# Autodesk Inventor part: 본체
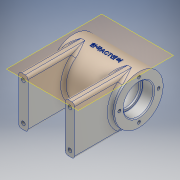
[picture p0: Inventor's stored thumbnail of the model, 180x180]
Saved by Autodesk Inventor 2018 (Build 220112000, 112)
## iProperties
Created: 2020-07
Part Number: 본체
Material: 알루미늄 6061
Document SubType Name: Modeling
Designer: Administrator
Density: 2.7 g/cm^3
Appearance: 알루미늄 - 평지
Mass: 305.265 g
Surface Area: 357.573 cm^2
Volume: 113.061 cm^3
Author: Administrator
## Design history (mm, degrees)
sketch "스케치1"
  geometry: L1 (-35, 0)-(35, 0); L2 (-35, 26)-(-35, 0); L3 (-35, 26)-(35, 26); L4 (35, 26)-(35, 0); L5 (-35, 16)-(-23, 16); L6 (-23, 16)-(-23, 14); L7 (-23, 14)-(-21, 14); L8 (-21, 14)-(-21, 21); L9 (-21, 21)-(21, 21); L10 (21, 21)-(21, 14); L11 (21, 14)-(23, 14); L12 (23, 14)-(23, 16); L13 (23, 16)-(35, 16); 3 further points
  constraints: 26 end point, 7 perpendicular, 6 point on line, 2 horizontal, 2 midpoint, 1 coincident, 1 vertical, 1 vertical alignment
  dimensions: "d0" = 70 distance of L1.start L1.end; "d1" = 32 diameter of L5 L1; "d2" = 42 diameter of L9 L1; "d3" = 52 diameter of L3 L1; "d4" = 12 distance of L5.start L5.end; "d5" = 12 distance of L12.end L13.end; "d7" = 28 diameter of L7 L1; "d8" = 42 distance of L8.end L9.end
revolve "회전1" sketch "스케치1" stored, may be unused: angle "d9" = 90 deg
node "작업 평면1"
sketch "스케치2"
  geometry: L1 (30, -26)-(30, 26); L2 (30, 26)-(20, 26); L3 (20, 26)-(20, -26); L4 (20, -26)-(30, -26); L5 (-20, -26)-(-30, -26); L6 (-30, -26)-(-30, 26); L7 (-30, 26)-(-20, 26); L8 (-20, 26)-(-20, -26); 2 further points
  constraints: 16 end point, 4 perpendicular, 2 horizontal alignment, 2 parallel, 1 horizontal, 1 midpoint, 1 vertical
  dimensions: "d11" = 60 distance between parallel lines of L6 L1; "d12" = 10 distance of L1.end L2.end; "d13" = 10 distance of L6.end L7.end; "d16" = 20 distance from line of point (0, 0) L3; "d19" = 52 distance of L1.start L1.end; "d20" = 52 distance of L5.end L6.end
extrude "돌출1" join sketch "스케치2" stored distance "d17" = 10; taper "d18" = 0 deg
node "작업 평면2"
sketch "스케치3"
  geometry: C1 r 5 at (0, 0); 1 further point
  constraints: 1 centre point, 1 coincident
  dimensions: "d22" = 10 diameter of C1
extrude "돌출2" join sketch "스케치3" stored distance "d23" = 10; taper "d24" = 0 deg
sketch "스케치4"
  geometry: C1 r 21 at (0, 0); 3 further points
  constraints: 2 vertical alignment, 1 centre point, 1 coincident, 1 other
  dimensions: "d25" = 42 diameter of C1
hole "구멍1" sketch "스케치4" at (0, 21) diameter "d26" = 3.242; stored, may be unused: countersink angle "d30" = 90 deg, drill point angle "d32" = 118 deg; dims "d27" = 8, "d28" = 4, "d29" = 2, "d31" = 10
fillet "모깎기1" dims "d36" = 3
fillet "모깎기2" dims "d37" = 3
fillet "모깎기3" dims "d38" = 3
chamfer "모따기1" distance "d39" = 1; stored, may be unused: second distance "d40" = 2, angle "d41" = 45 deg
fillet "모깎기4" dims "d42" = 2
hole "구멍2" diameter "d50" = 5.188; stored, may be unused: countersink angle "d54" = 90 deg, drill point angle "d56" = 118 deg; dims "d48" = 10, "d49" = 10, "d51" = 12, "d52" = 4, "d53" = 2, "d55" = 16
sketch "스케치6"
  geometry: L1 (0, 0)-(-48.238, -17.557); L2 (0, 26)-(-64, 26) reference; L3 (-27.251, -9.919)-(-25.199, -15.557); L4 (-25.199, -15.557)-(-20.535, -13.859); L5 (-20.535, -13.859)-(-22.587, -8.221); C1 r 14 at (0, 0) reference; A1 r 29 centre (0, 0) between (-17.664, 23) and (-17.664, -23) reference; 1 further point
  constraints: 8 end point, 2 parallel, 2 point on line, 1 perpendicular
  dimensions: "d58" = 20 deg angle of L2 L1; "d59" = 29 distance from line of point (0, 0) L3; "d60" = 12 diameter of L4 L1; "d61" = 4.96314 distance between parallel lines of L5 L3; "d62" = 43.55733 distance from line of L1.end L2
revolve "회전2" sketch "스케치6" stored, may be unused: angle "d63" = 90 deg
hole "구멍3" diameter "d66" = 5.188; stored, may be unused: countersink angle "d70" = 90 deg, drill point angle "d72" = 118 deg; dims "d64" = 10, "d65" = 10, "d67" = 12, "d68" = 4, "d69" = 2, "d71" = 16
fillet "모깎기5" dims "d73" = 2
sketch "스케치7"
  geometry: 3 further points
  constraints: 1 vertical alignment
  dimensions: "d74" = 25 horizontal distance of point (0, 0) point (25, -20); "d75" = 40 distance of point (25, 20) point (25, -20); "d76" = 20 vertical distance of point (0, 0) point (25, -20)
hole "구멍4" sketch "스케치7" at (25, -20), (25, 20) diameter "d77" = 4.134; stored, may be unused: countersink angle "d81" = 90 deg, drill point angle "d83" = 118 deg; dims "d78" = 8, "d79" = 4, "d80" = 2, "d82" = 10
fillet "모깎기6" dims "d84" = 3
fillet "모깎기7" dims "d85" = 0.3
node "작업 평면4"
sketch "스케치8"
  geometry: L1 (-35, 26)-(35, 26) reference; L2 (-35, -26)-(-35, 26) reference; 2 further points
  constraints: 1 other
  dimensions: "d86" = 26 distance from line of L1 point (0, 0); "d87" = 35 distance from line of point (0, 0) L2
feature "엠보싱1" sketch "스케치8" dims "d0" = 70, "d1" = 32, "d2" = 42, "d3" = 52, "d4" = 12, "d5" = 12, "d7" = 28, "d8" = 42, "d88" = 0.5, "d89" = 0
node "솔리드1"
pattern_circular "원형 패턴1" dims angle "d34" = 360 deg
mirror "미러1"
mirror "미러2"
other parameters: "d10" = -64, "d21" = 29
